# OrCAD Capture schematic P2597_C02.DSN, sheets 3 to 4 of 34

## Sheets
3 31_Power Monitor I: size Custom
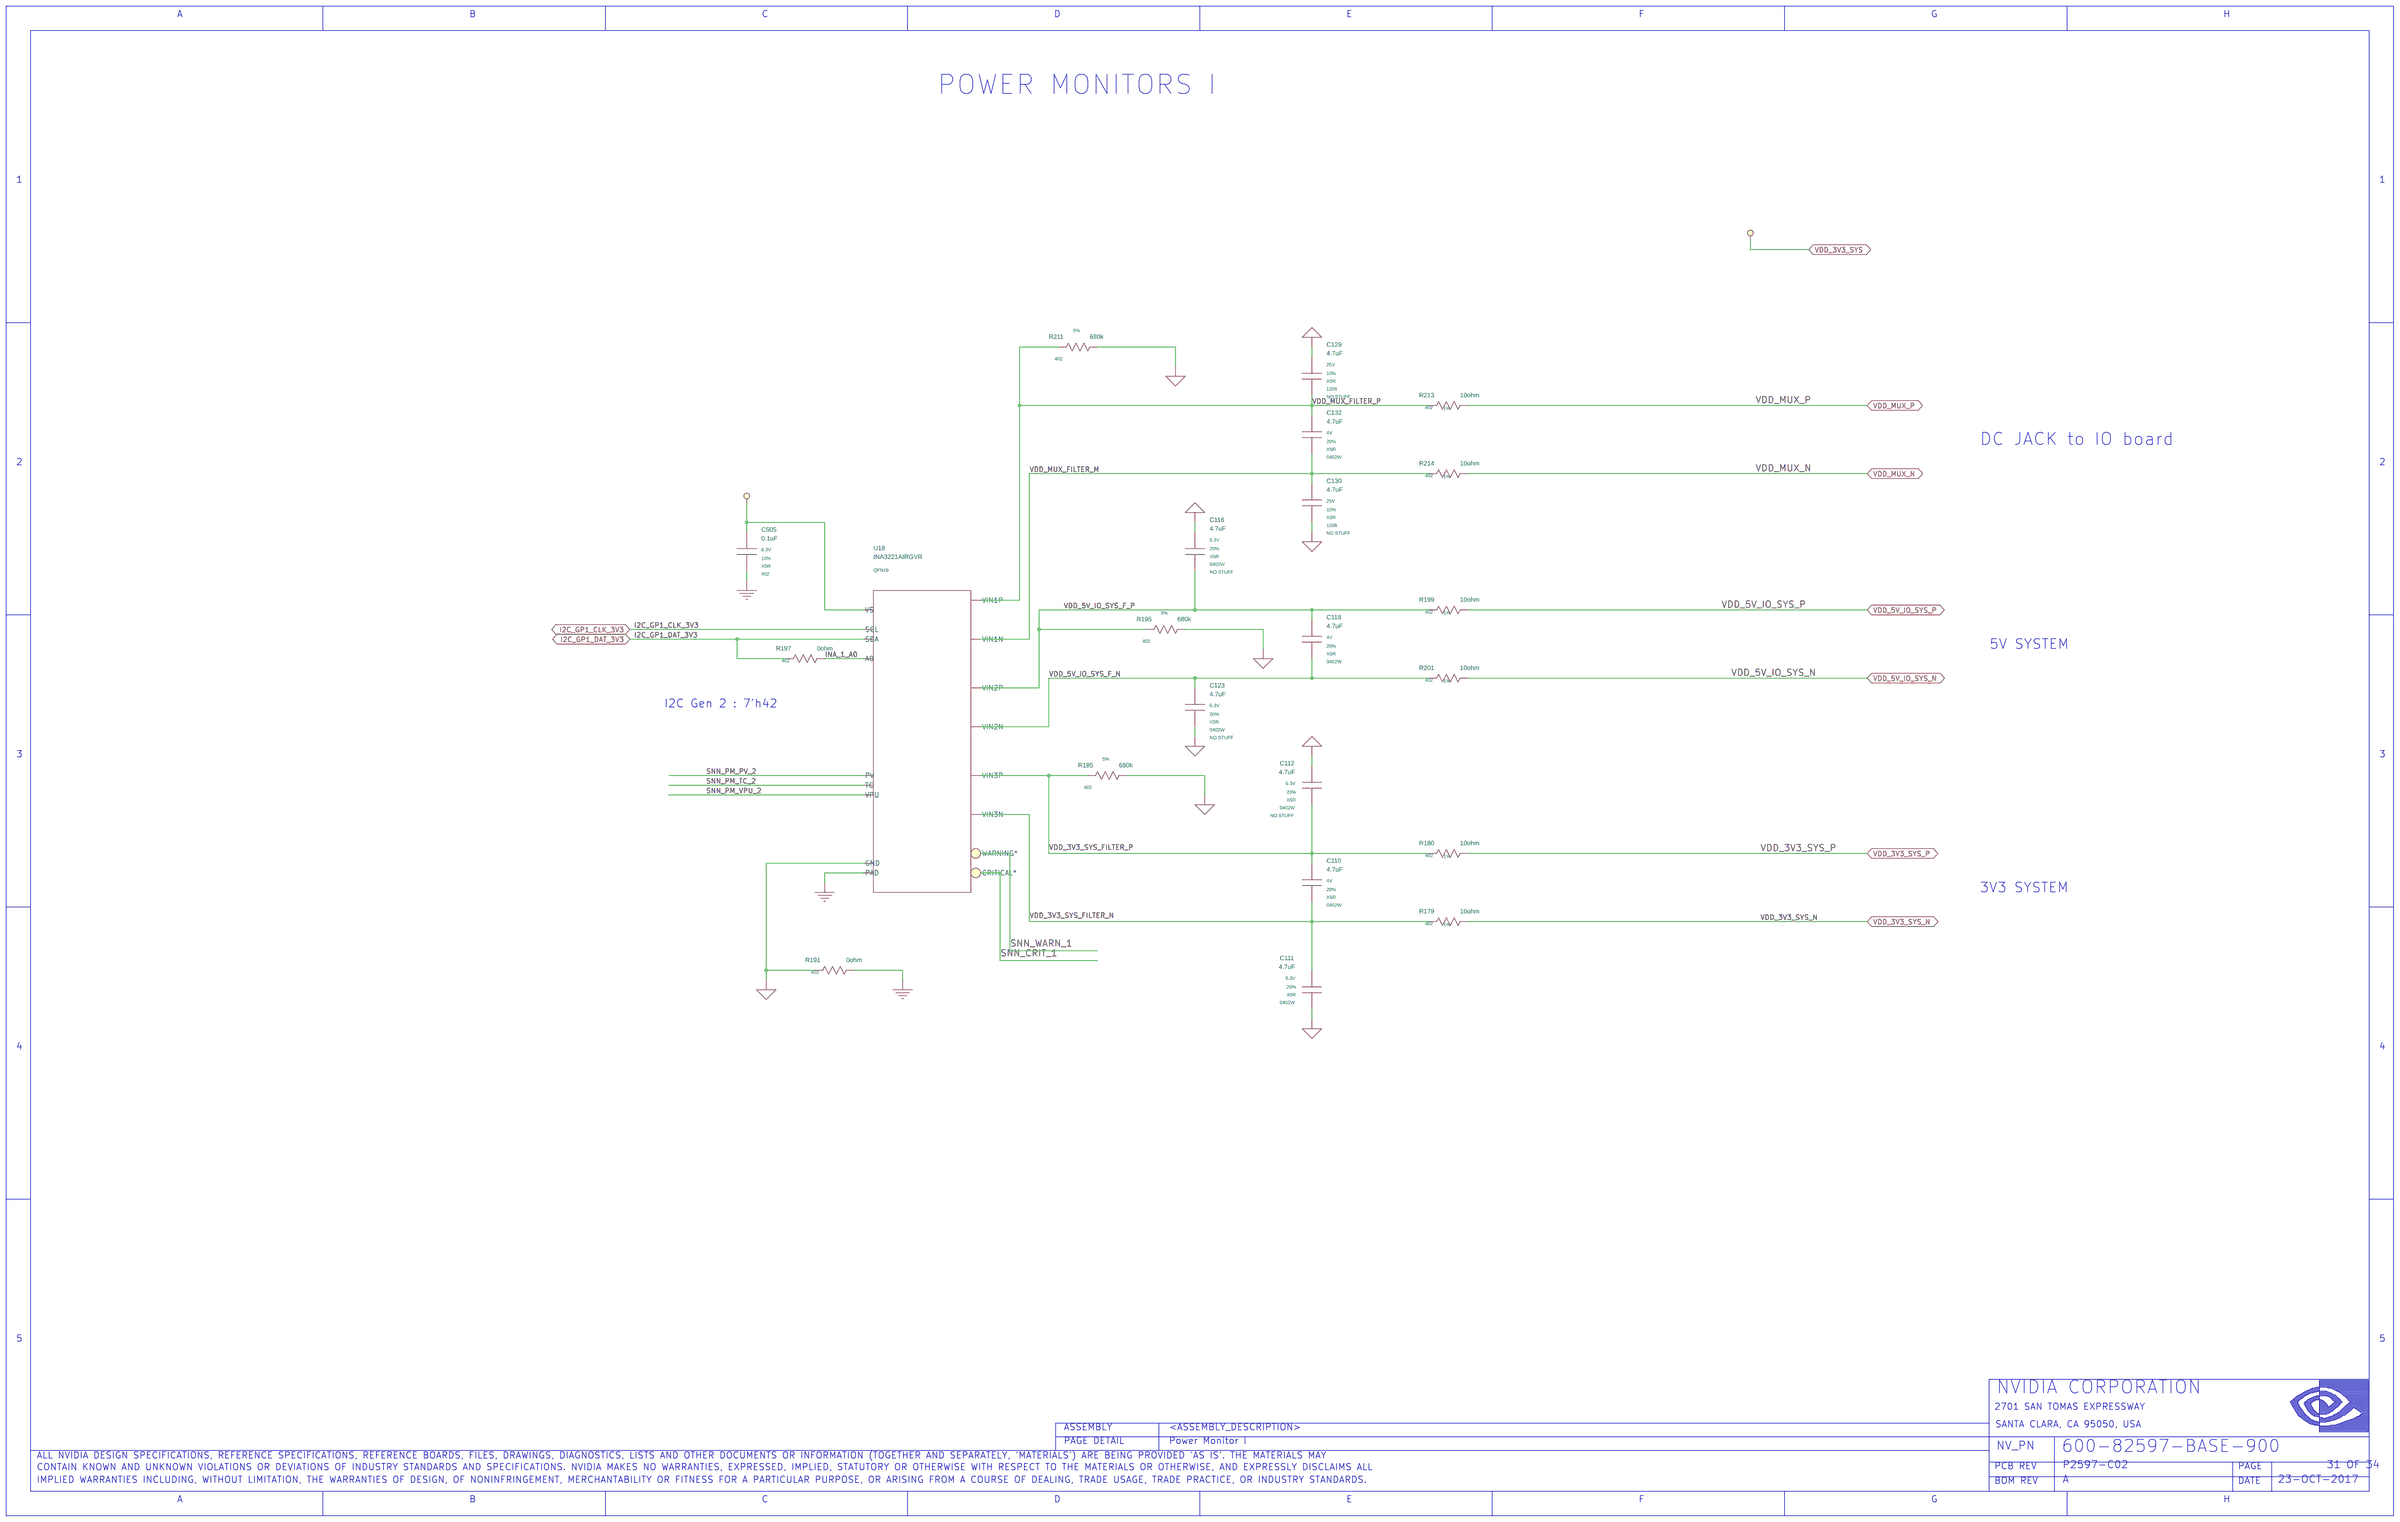
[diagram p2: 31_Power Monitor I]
4 30_Rail Discharge: size Custom
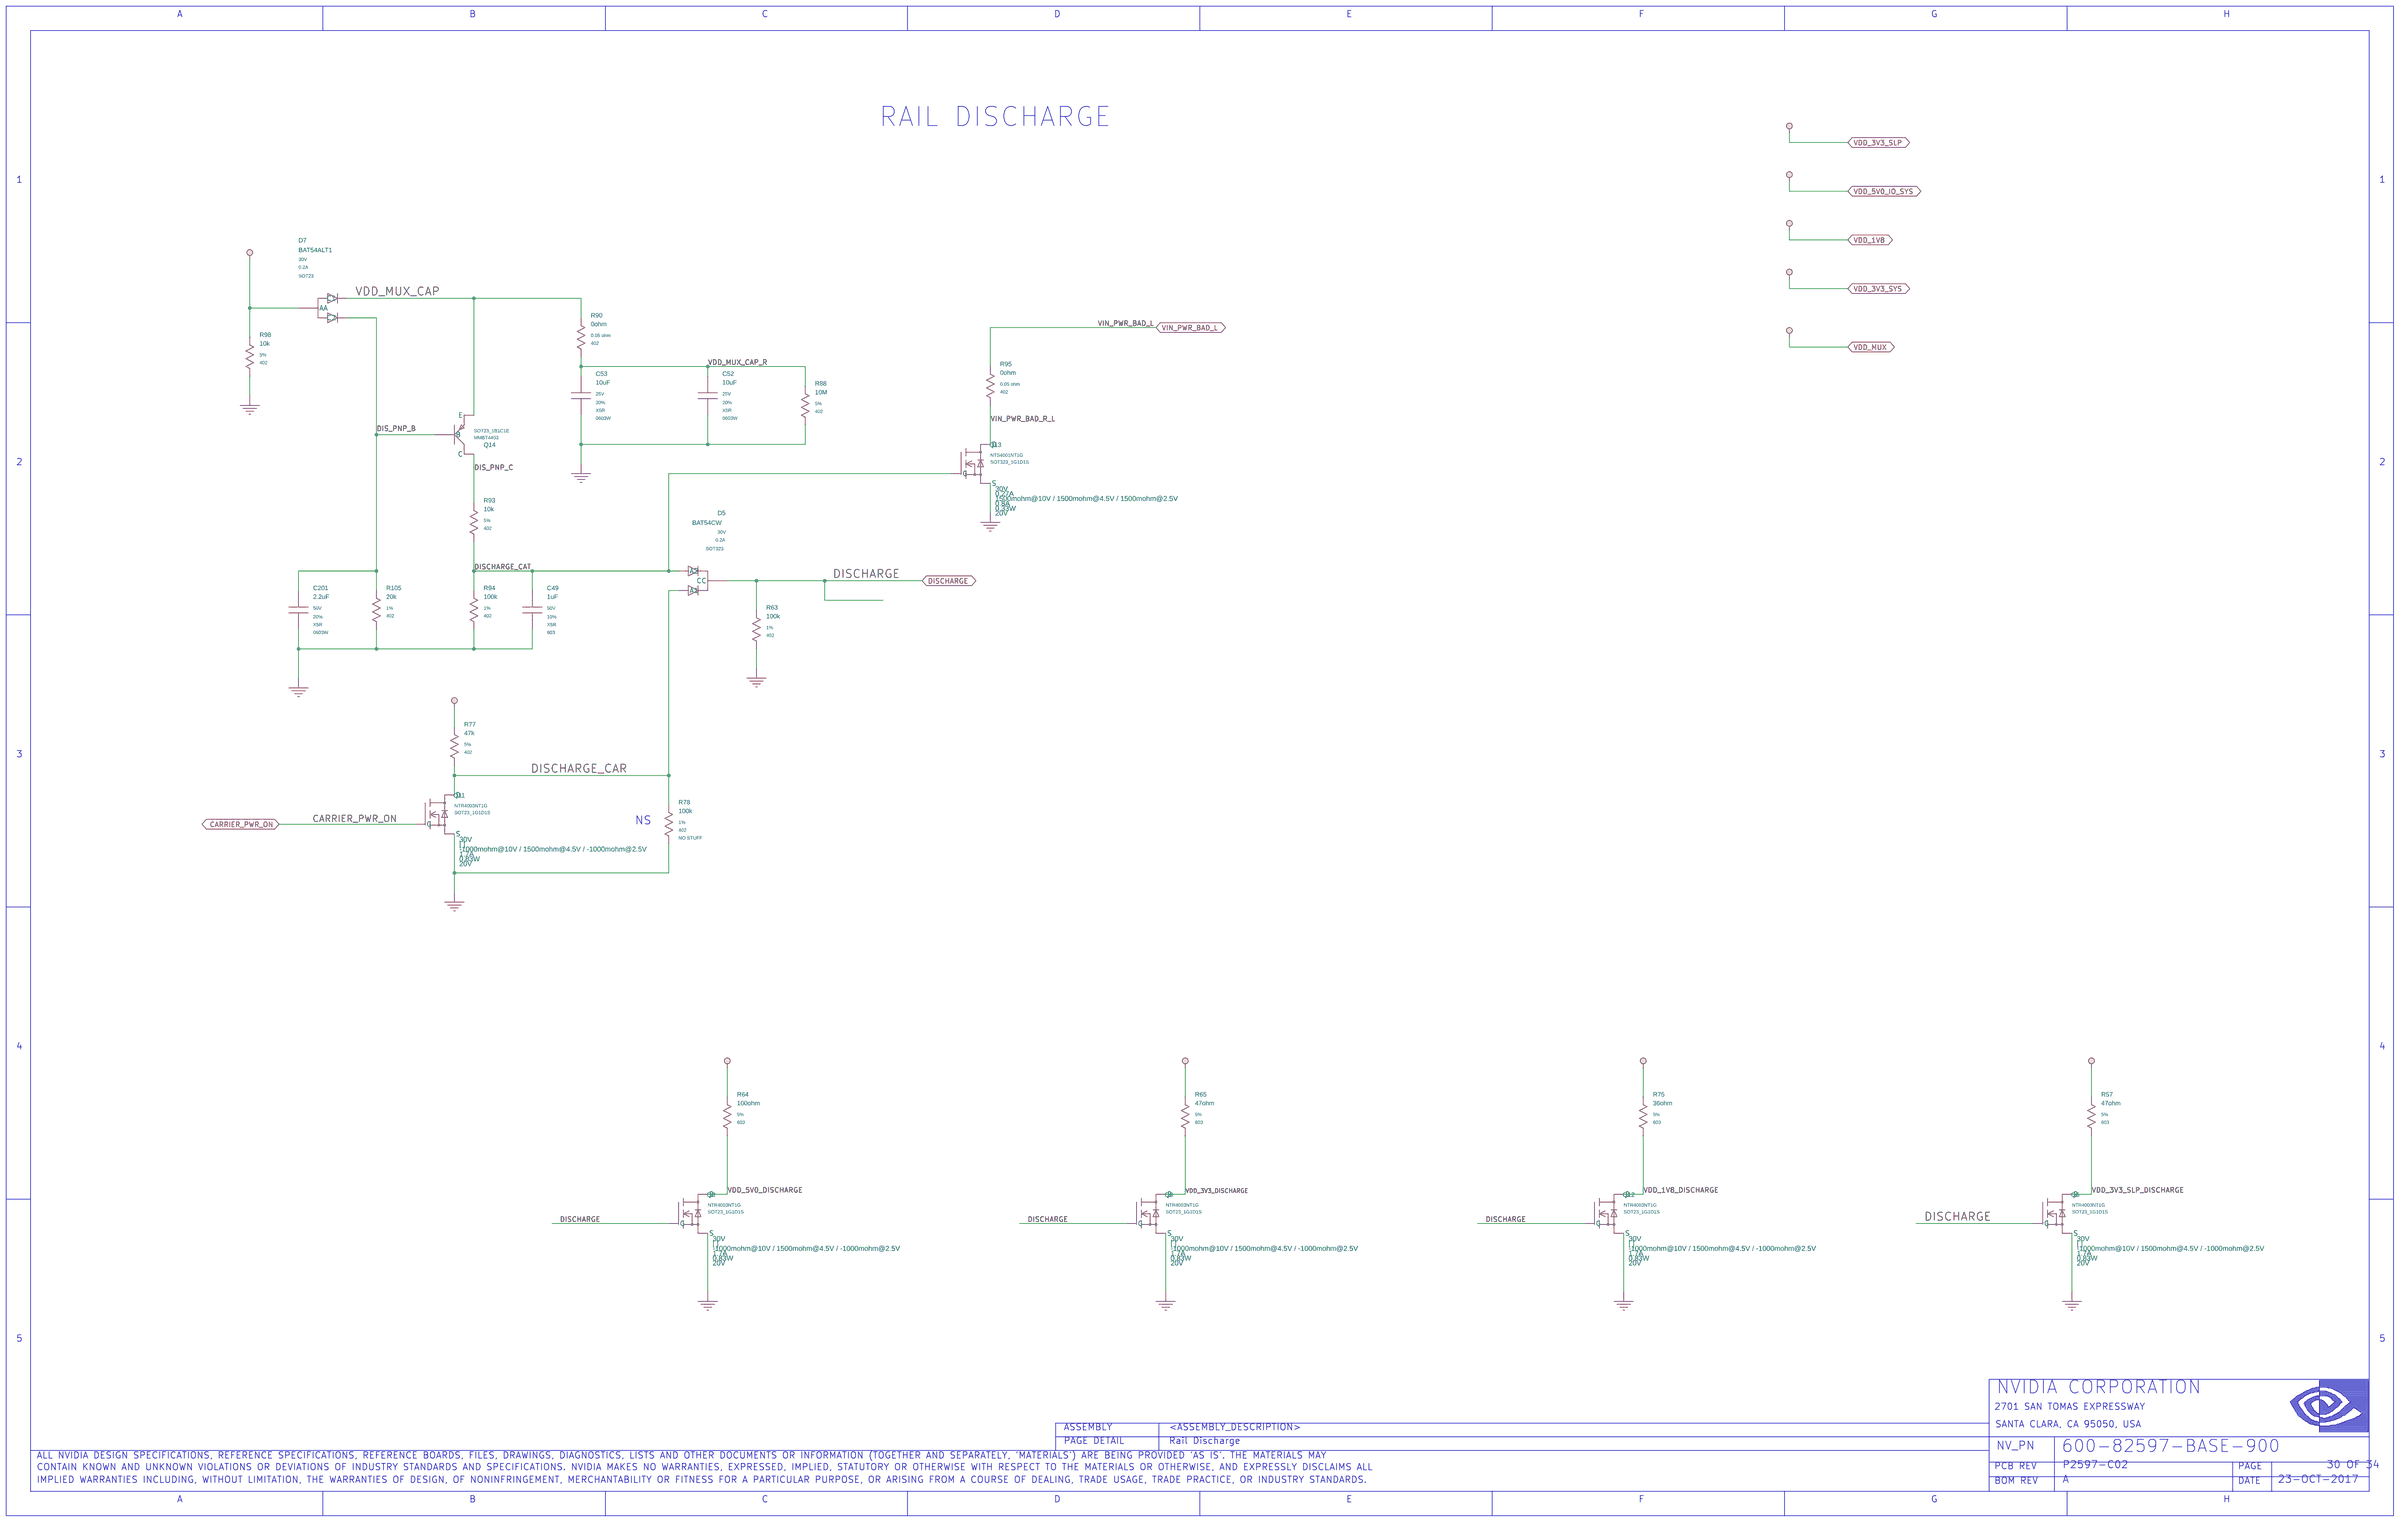
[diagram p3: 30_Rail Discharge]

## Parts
sheet 30_Rail Discharge
C49  1uF  [603]
C52  10uF  [0603_LARGE]
C53  10uF  [0603_LARGE]
C201  2.2uF  [0603_LARGE]
D5  D_3PIN_CC  [SOT323]
D7  D_3PIN_AA  [SOT23]
Q6  Q_FET_N_ENH  [SOT23]
Q8  Q_FET_N_ENH  [SOT23]
Q9  Q_FET_N_ENH  [SOT23]
Q11  Q_FET_N_ENH  [SOT23]
Q12  Q_FET_N_ENH  [SOT23]
Q13  Q_FET_N_ENH  [SOT323]
Q14  Q_PNP  [SOT23]
R57  47ohm  [603]
R63  100k  [402]
R64  100ohm  [603]
R65  47ohm  [603]
R75  36ohm  [603]
R77  47k  [402]
R78  100k  [402]
R88  10M  [402]
R90  0ohm  [402]
R93  10k  [402]
R94  100k  [402]
R95  0ohm  [402]
R98  10k  [402]
R105  20k  [402]
sheet 31_Power Monitor I
C110  4.7uF  [0402_LARGE]
C111  4.7uF  [0402_LARGE]
C112  4.7uF  [0402_LARGE]
C116  4.7uF  [0402_LARGE]
C118  4.7uF  [0402_LARGE]
C123  4.7uF  [0402_LARGE]
C129  4.7uF  [1206]
C130  4.7uF  [1206]
C132  4.7uF  [0402_LARGE]
C505  0.1uF  [402]
R179  10ohm  [402]
R180  10ohm  [402]
R185  680k  [402]
R191  0ohm  [402]
R195  680k  [402]
R197  0ohm  [402]
R199  10ohm  [402]
R201  10ohm  [402]
R211  680k  [402]
R213  10ohm  [402]
R214  10ohm  [402]
U18  U_PWRMTR_INA3221  [QFN016Q_P065_0047_T022X022]

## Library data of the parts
C49 = C: ASSEMBLY: PWR_DIS; CDS_LIB: discrete; CDS_PART_NAME: C_0603-1UF,X5R,10%,50V,039-0222-000; CDS_PHYS_PART_NAME: C_0603-1UF,X5R,10%,50V,039-0222-000-039-0222-000,1UF; CDS_SEC: 1; DEVICE_TYPENAME: C_0603-1UFX5R1050V039-0222-000-039-0222-0001UF; DRAWING: @P2597_C02_LIB.P2597_C02(SCH_1):PAGE30; MAT: X5R; MAX_VOLTAGE: 50V; NV_PN: 039-0222-000; PATH: I14; PHYS_PAGE: 30; ROT: 0; SEC: 1; SIGNAL_MODEL: nv_cap; TOL: 10%; VER: 1; XY: (-9450,4500)
C52 = C: ASSEMBLY: PWR_DIS; CDS_LIB: discrete; CDS_PART_NAME: C_0603W-10UF,X5R,20%,25V,032-0186-000; CDS_PHYS_PART_NAME: C_0603W-10UF,X5R,20%,25V,032-0186-000-032-0186-000,10UF; CDS_SEC: 1; DEVICE_TYPENAME: C_0603W-10UFX5R2025V032-0186-000-032-0186-00010UF; DRAWING: @P2597_C02_LIB.P2597_C02(SCH_1):PAGE30; MAT: X5R; MAX_VOLTAGE: 25V; NV_PN: 032-0186-000; PACK_TYPE: 0603W; PATH: I35; PHYS_PAGE: 30; ROT: 0; SEC: 1; SIGNAL_MODEL: nv_cap; TOL: 20%; VER: 1; XY: (-8550,5600)
C53 = C: ASSEMBLY: PWR_DIS; CDS_LIB: discrete; CDS_PART_NAME: C_0603W-10UF,X5R,20%,25V,032-0186-000; CDS_PHYS_PART_NAME: C_0603W-10UF,X5R,20%,25V,032-0186-000-032-0186-000,10UF; CDS_SEC: 1; DEVICE_TYPENAME: C_0603W-10UFX5R2025V032-0186-000-032-0186-00010UF; DRAWING: @P2597_C02_LIB.P2597_C02(SCH_1):PAGE30; MAT: X5R; MAX_VOLTAGE: 25V; NV_PN: 032-0186-000; PACK_TYPE: 0603W; PATH: I36; PHYS_PAGE: 30; ROT: 0; SEC: 1; SIGNAL_MODEL: nv_cap; TOL: 20%; VER: 1; XY: (-9200,5600)
C201 = C: ASSEMBLY: PWR_DIS; CDS_LIB: discrete; CDS_PART_NAME: C_0603W-2.2UF,X5R,20%,50V,032-0201-000; CDS_PHYS_PART_NAME: C_0603W-2.2UF,X5R,20%,50V,032-0201-000-032-0201-000,2.2UF; CDS_SEC: 1; DEVICE_TYPENAME: C_0603W-22UFX5R2050V032-0201-000-032-0201-00022UF; DRAWING: @P2597_C02_LIB.P2597_C02(SCH_1):PAGE30; MAT: X5R; MAX_VOLTAGE: 50V; NV_PN: 032-0201-000; PACK_TYPE: 0603W; PATH: I68; PHYS_PAGE: 30; ROT: 0; SEC: 1; SEC_TYPE: 0603W; SIGNAL_MODEL: nv_cap; TOL: 20%; VER: 1; XY: (-10650,4500)
D5 = D_3PIN_CC: ASSEMBLY: PWR_DIS; CDS_LIB: discrete; CDS_PART_NAME: D_3PIN_CC_SOT323-BAT54CW,1 PAIR - COMMON CATHODE,30V,0.6A,1V@0.1A,0.2A,091-0022-000; CDS_PHYS_PART_NAME: D_3PIN_CC_SOT323-BAT54CW,1 PAIR - COMMON CATHODE,30V,0.6A,1V@0.1A,0.2A,091-0022-000-091-0022-000; CDS_SEC: 1; CONFIGURATION: 1 Pair - Common Cathode; CONTINUOUS_CURRENT: 0.2A; DEVICE_TYPENAME: D_3PIN_CC_SOT323-BAT54CW1PAIR-COMMONCATHODE30V06A1V01A02A091-0022-000-091-0022-000; DRAWING: @P2597_C02_LIB.P2597_C02(SCH_1):PAGE30; FORWARD_VOLTAGE: 1V@0.1A; MAX_CURRENT: 0.6A; MAX_VOLTAGE: 30V; NV_NAME: BAT54CW; NV_PN: 091-0022-000; PATH: I46; PHYS_PAGE: 30; ROT: 2; SEC: 1; VER: 1; XY: (-8550,4650)
D7 = D_3PIN_AA: ASSEMBLY: PWR_DIS; CDS_LIB: discrete; CDS_PART_NAME: D_3PIN_AA_SOT23-BAT54ALT1,1 PAIR - COMMON ANODE,30V,0.6A,0.8V@0.1A,0.2A,091-0004-000; CDS_PHYS_PART_NAME: D_3PIN_AA_SOT23-BAT54ALT1,1 PAIR - COMMON ANODE,30V,0.6A,0.8V@0.1A,0.2A,091-0004-000-091-0004-000; CDS_SEC: 1; CONFIGURATION: 1 Pair - Common Anode; CONTINUOUS_CURRENT: 0.2A; DEVICE_TYPENAME: D_3PIN_AA_SOT23-BAT54ALT11PAIR-COMMONANODE30V06A08V01A02A091-0004-000-091-0004-000; DRAWING: @P2597_C02_LIB.P2597_C02(SCH_1):PAGE30; FORWARD_VOLTAGE: 0.8V@0.1A; MAX_CURRENT: 0.6A; MAX_VOLTAGE: 30V; NV_NAME: BAT54ALT1; NV_PN: 091-0004-000; PATH: I2; PHYS_PAGE: 30; ROT: 0; SEC: 1; VER: 1; XY: (-10550,6050)
Q6 = Q_FET_N_ENH#2: ASSEMBLY: PWR_DIS; CDS_LIB: discrete; CDS_PART_NAME: Q_FET_N_ENH_SOT23_1G1D1S-NTR4003NT1G,30V,-1000MOHM@10V / 1500MOHM@4.5V / -1000MOHM@2.5V,[ ],1.7A,20V,0.83W,[ ]@10V / [ ]@4.5V A; CDS_PHYS_PART_NAME: Q_FET_N_ENH_SOT23_1G1D1S-NTR4003NT1G,30V,-1000MOHM@10V / 1500MOHM@4.5V / -1000MOHM@2.5V,[ ],1.7A,20V,0.83W,[ ]@10V / [ ]@4.5V B; CDS_SEC: 1; CONTINUOUS_CURRENT: [ ]; CaptureCellPackProp: Q_FET_N_ENH__sym_2##2; DEVICE_TYPENAME: Q_FET_N_ENH_SOT23_1G1D1S-NTR4003NT1G30V-1000MOHM10V1500MOHM45V-1000MOHM25V17A20V083W10V45VB; DRAWING: @P2597_C02_LIB.P2597_C02(SCH_1):PAGE30; MAX_CURRENT: 1.7A; MAX_VOLTAGE: 30V; MAX_WATTAGE: 0.83W; NV_NAME: NTR4003NT1G; NV_PN: 300-0381-000; PACK_TYPE: SOT23_1G1D1S; PATH: I43; PHYS_PAGE: 30; Q_G: [ ]@10V / [ ]@4.5V / [ ]@2.5V; ROT: 0; R_DS_ON: -1000mohm@10V / 1500mohm@4.5V / -1000mohm@2.5V; SEC: 1; VER: 2; V_BE_GS: 20V; XY: (-1650,1400)
Q8 = Q_FET_N_ENH#2: ASSEMBLY: PWR_DIS; CDS_LIB: discrete; CDS_PART_NAME: Q_FET_N_ENH_SOT23_1G1D1S-NTR4003NT1G,30V,-1000MOHM@10V / 1500MOHM@4.5V / -1000MOHM@2.5V,[ ],1.7A,20V,0.83W,[ ]@10V / [ ]@4.5V A; CDS_PHYS_PART_NAME: Q_FET_N_ENH_SOT23_1G1D1S-NTR4003NT1G,30V,-1000MOHM@10V / 1500MOHM@4.5V / -1000MOHM@2.5V,[ ],1.7A,20V,0.83W,[ ]@10V / [ ]@4.5V B; CDS_SEC: 1; CONTINUOUS_CURRENT: [ ]; CaptureCellPackProp: Q_FET_N_ENH__sym_2##2; DEVICE_TYPENAME: Q_FET_N_ENH_SOT23_1G1D1S-NTR4003NT1G30V-1000MOHM10V1500MOHM45V-1000MOHM25V17A20V083W10V45VB; DRAWING: @P2597_C02_LIB.P2597_C02(SCH_1):PAGE30; MAX_CURRENT: 1.7A; MAX_VOLTAGE: 30V; MAX_WATTAGE: 0.83W; NV_NAME: NTR4003NT1G; NV_PN: 300-0381-000; PACK_TYPE: SOT23_1G1D1S; PATH: I17; PHYS_PAGE: 30; Q_G: [ ]@10V / [ ]@4.5V / [ ]@2.5V; ROT: 0; R_DS_ON: -1000mohm@10V / 1500mohm@4.5V / -1000mohm@2.5V; SEC: 1; VER: 2; V_BE_GS: 20V; XY: (-8650,1400)
Q9 = Q_FET_N_ENH#2: ASSEMBLY: PWR_DIS; CDS_LIB: discrete; CDS_PART_NAME: Q_FET_N_ENH_SOT23_1G1D1S-NTR4003NT1G,30V,-1000MOHM@10V / 1500MOHM@4.5V / -1000MOHM@2.5V,[ ],1.7A,20V,0.83W,[ ]@10V / [ ]@4.5V A; CDS_PHYS_PART_NAME: Q_FET_N_ENH_SOT23_1G1D1S-NTR4003NT1G,30V,-1000MOHM@10V / 1500MOHM@4.5V / -1000MOHM@2.5V,[ ],1.7A,20V,0.83W,[ ]@10V / [ ]@4.5V B; CDS_SEC: 1; CONTINUOUS_CURRENT: [ ]; CaptureCellPackProp: Q_FET_N_ENH__sym_2##2; DEVICE_TYPENAME: Q_FET_N_ENH_SOT23_1G1D1S-NTR4003NT1G30V-1000MOHM10V1500MOHM45V-1000MOHM25V17A20V083W10V45VB; DRAWING: @P2597_C02_LIB.P2597_C02(SCH_1):PAGE30; MAX_CURRENT: 1.7A; MAX_VOLTAGE: 30V; MAX_WATTAGE: 0.83W; NV_NAME: NTR4003NT1G; NV_PN: 300-0381-000; PACK_TYPE: SOT23_1G1D1S; PATH: I24; PHYS_PAGE: 30; Q_G: [ ]@10V / [ ]@4.5V / [ ]@2.5V; ROT: 0; R_DS_ON: -1000mohm@10V / 1500mohm@4.5V / -1000mohm@2.5V; SEC: 1; VER: 2; V_BE_GS: 20V; XY: (-6300,1400)
Q11 = Q_FET_N_ENH#2: ASSEMBLY: PWR_DIS; CDS_LIB: discrete; CDS_PART_NAME: Q_FET_N_ENH_SOT23_1G1D1S-NTR4003NT1G,30V,-1000MOHM@10V / 1500MOHM@4.5V / -1000MOHM@2.5V,[ ],1.7A,20V,0.83W,[ ]@10V / [ ]@4.5V A; CDS_PHYS_PART_NAME: Q_FET_N_ENH_SOT23_1G1D1S-NTR4003NT1G,30V,-1000MOHM@10V / 1500MOHM@4.5V / -1000MOHM@2.5V,[ ],1.7A,20V,0.83W,[ ]@10V / [ ]@4.5V B; CDS_SEC: 1; CONTINUOUS_CURRENT: [ ]; CaptureCellPackProp: Q_FET_N_ENH__sym_2##2; DEVICE_TYPENAME: Q_FET_N_ENH_SOT23_1G1D1S-NTR4003NT1G30V-1000MOHM10V1500MOHM45V-1000MOHM25V17A20V083W10V45VB; DRAWING: @P2597_C02_LIB.P2597_C02(SCH_1):PAGE30; MAX_CURRENT: 1.7A; MAX_VOLTAGE: 30V; MAX_WATTAGE: 0.83W; NV_NAME: NTR4003NT1G; NV_PN: 300-0381-000; PACK_TYPE: SOT23_1G1D1S; PATH: I47; PHYS_PAGE: 30; Q_G: [ ]@10V / [ ]@4.5V / [ ]@2.5V; ROT: 0; R_DS_ON: -1000mohm@10V / 1500mohm@4.5V / -1000mohm@2.5V; SEC: 1; VER: 2; V_BE_GS: 20V; XY: (-9950,3450)
Q12 = Q_FET_N_ENH#2: ASSEMBLY: PWR_DIS; CDS_LIB: discrete; CDS_PART_NAME: Q_FET_N_ENH_SOT23_1G1D1S-NTR4003NT1G,30V,-1000MOHM@10V / 1500MOHM@4.5V / -1000MOHM@2.5V,[ ],1.7A,20V,0.83W,[ ]@10V / [ ]@4.5V A; CDS_PHYS_PART_NAME: Q_FET_N_ENH_SOT23_1G1D1S-NTR4003NT1G,30V,-1000MOHM@10V / 1500MOHM@4.5V / -1000MOHM@2.5V,[ ],1.7A,20V,0.83W,[ ]@10V / [ ]@4.5V B; CDS_SEC: 1; CONTINUOUS_CURRENT: [ ]; CaptureCellPackProp: Q_FET_N_ENH__sym_2##2; DEVICE_TYPENAME: Q_FET_N_ENH_SOT23_1G1D1S-NTR4003NT1G30V-1000MOHM10V1500MOHM45V-1000MOHM25V17A20V083W10V45VB; DRAWING: @P2597_C02_LIB.P2597_C02(SCH_1):PAGE30; MAX_CURRENT: 1.7A; MAX_VOLTAGE: 30V; MAX_WATTAGE: 0.83W; NV_NAME: NTR4003NT1G; NV_PN: 300-0381-000; PACK_TYPE: SOT23_1G1D1S; PATH: I29; PHYS_PAGE: 30; Q_G: [ ]@10V / [ ]@4.5V / [ ]@2.5V; ROT: 0; R_DS_ON: -1000mohm@10V / 1500mohm@4.5V / -1000mohm@2.5V; SEC: 1; VER: 2; V_BE_GS: 20V; XY: (-3950,1400)
Q13 = Q_FET_N_ENH#2: ASSEMBLY: CONN_POWER; CDS_LIB: discrete; CDS_PART_NAME: Q_FET_N_ENH_SOT323_1G1D1S-NTS4001NT1G,30V,1500MOHM@10V / 1500MOHM@4.5V / 1500MOHM@2.5V,0.27A,0.8A,20V,0.33W,[ ]@10V / [ ]@4.5VA; CDS_PHYS_PART_NAME: Q_FET_N_ENH_SOT323_1G1D1S-NTS4001NT1G,30V,1500MOHM@10V / 1500MOHM@4.5V / 1500MOHM@2.5V,0.27A,0.8A,20V,0.33W,[ ]@10V / [ ]@4.5VB; CDS_SEC: 1; CONTINUOUS_CURRENT: 0.27A; CaptureCellPackProp: Q_FET_N_ENH__sym_2##2; DEVICE_TYPENAME: Q_FET_N_ENH_SOT323_1G1D1S-NTS4001NT1G30V1500MOHM10V1500MOHM45V1500MOHM25V027A08A20V033W10V45VB; DRAWING: @P2597_C02_LIB.P2597_C02(SCH_1):PAGE30; MAX_CURRENT: 0.8A; MAX_VOLTAGE: 30V; MAX_WATTAGE: 0.33W; NV_NAME: NTS4001NT1G; NV_PN: 300-0485-000; PACK_TYPE: SOT323_1G1D1S; PATH: I38; PHYS_PAGE: 30; Q_G: [ ]@10V / [ ]@4.5V / [ ]@2.5V; ROT: 0; R_DS_ON: 1500mohm@10V / 1500mohm@4.5V / 1500mohm@2.5V; SEC: 1; SEC_TYPE: SOT323_1G1D1S; VER: 2; V_BE_GS: 20V; XY: (-7200,5250)
Q14 = Q_PNP: ASSEMBLY: PWR_DIS; CDS_LIB: discrete; CDS_PART_NAME: Q_PNP_SOT23_1B1C1E-MMBT4403,40V,[ ],0.6A,0.6A,5V,0.225W,305-0002-000; CDS_PHYS_PART_NAME: Q_PNP_SOT23_1B1C1E-MMBT4403,40V,[ ],0.6A,0.6A,5V,0.225W,305-0002-000-305-0002-000; CDS_SEC: 1; CONTINUOUS_CURRENT: 0.6A; DEVICE_TYPENAME: Q_PNP_SOT23_1B1C1E-MMBT440340V06A06A5V0225W305-0002-000-305-0002-000; DRAWING: @P2597_C02_LIB.P2597_C02(SCH_1):PAGE30; MAX_CURRENT: 0.6A; MAX_VOLTAGE: 40V; MAX_WATTAGE: 0.225W; NV_NAME: MMBT4403; NV_PN: 305-0002-000; PACK_TYPE: SOT23_1B1C1E; PATH: I5; PHYS_PAGE: 30; ROT: 6; SEC: 1; VER: 1; V_BE_GS: 5V; V_CE_SAT: [ ]; XY: (-9850,5400)
R57 = R#1: ASSEMBLY: PWR_DIS; CDS_LIB: discrete; CDS_PART_NAME: R_0603-47OHM,5 %,0.1W,195-1246-000; CDS_PHYS_PART_NAME: R_0603-47OHM,5 %,0.1W,195-1246-000-195-1246-000,47OHM; CDS_SEC: 1; CHIPS_PART_NAME: R; DEVICE_TYPENAME: R_0603-47OHM501W195-1246-000-195-1246-00047OHM; DRAWING: @P2597_C02_LIB.P2597_C02(SCH_1):PAGE30; MAX_WATTAGE: 0.1W; NV_PN: 195-1246-000; PATH: I42; PHYS_PAGE: 30; ROT: 0; SEC: 1; SIGNAL_MODEL: nv_res; TOL: 5%; VER: 2; XY: (-1450,1900)
R63 = R#1: ASSEMBLY: PWR_DIS; CDS_LIB: discrete; CDS_PART_NAME: R_0402-100K,1 %,62.5MW,195-0005-000; CDS_PHYS_PART_NAME: R_0402-100K,1 %,62.5MW,195-0005-000-100K,195-0005-000; CDS_SEC: 1; CHIPS_PART_NAME: R; DEVICE_TYPENAME: R_0402-100K1625MW195-0005-000-100K195-0005-000; DRAWING: @P2597_C02_LIB.P2597_C02(SCH_1):PAGE30; MAX_WATTAGE: 62.5mW; NV_PN: 195-0005-000; PATH: I53; PHYS_PAGE: 30; ROT: 0; SEC: 1; SIGNAL_MODEL: nv_res; TOL: 1%; VER: 2; XY: (-8300,4400)
R64 = R#1: ASSEMBLY: PWR_DIS; CDS_LIB: discrete; CDS_PART_NAME: R_0603-100OHM,5 %,0.1W,195-1134-000; CDS_PHYS_PART_NAME: R_0603-100OHM,5 %,0.1W,195-1134-000-100OHM,195-1134-000; CDS_SEC: 1; CHIPS_PART_NAME: R; DEVICE_TYPENAME: R_0603-100OHM501W195-1134-000-100OHM195-1134-000; DRAWING: @P2597_C02_LIB.P2597_C02(SCH_1):PAGE30; MAX_WATTAGE: 0.1W; NV_PN: 195-1134-000; PATH: I19; PHYS_PAGE: 30; ROT: 0; SEC: 1; SIGNAL_MODEL: nv_res; TOL: 5%; VER: 2; XY: (-8450,1900)
R65 = R#1: ASSEMBLY: PWR_DIS; CDS_LIB: discrete; CDS_PART_NAME: R_0603-47OHM,5 %,0.1W,195-1246-000; CDS_PHYS_PART_NAME: R_0603-47OHM,5 %,0.1W,195-1246-000-195-1246-000,47OHM; CDS_SEC: 1; CHIPS_PART_NAME: R; DEVICE_TYPENAME: R_0603-47OHM501W195-1246-000-195-1246-00047OHM; DRAWING: @P2597_C02_LIB.P2597_C02(SCH_1):PAGE30; MAX_WATTAGE: 0.1W; NV_PN: 195-1246-000; PATH: I23; PHYS_PAGE: 30; ROT: 0; SEC: 1; SIGNAL_MODEL: nv_res; TOL: 5%; VER: 2; XY: (-6100,1900)
R75 = R#1: ASSEMBLY: PWR_DIS; CDS_LIB: discrete; CDS_PART_NAME: R_0603-36OHM,5 %,0.1W,195-1225-000; CDS_PHYS_PART_NAME: R_0603-36OHM,5 %,0.1W,195-1225-000-195-1225-000,36OHM; CDS_SEC: 1; CHIPS_PART_NAME: R; DEVICE_TYPENAME: R_0603-36OHM501W195-1225-000-195-1225-00036OHM; DRAWING: @P2597_C02_LIB.P2597_C02(SCH_1):PAGE30; MAX_WATTAGE: 0.1W; NV_PN: 195-1225-000; PATH: I28; PHYS_PAGE: 30; ROT: 0; SEC: 1; SIGNAL_MODEL: nv_res; TOL: 5%; VER: 2; XY: (-3750,1900)
R77 = R#1: ASSEMBLY: PWR_DIS; CDS_LIB: discrete; CDS_PART_NAME: R_0402-47K,5 %,62.5MW,195-0599-000; CDS_PHYS_PART_NAME: R_0402-47K,5 %,62.5MW,195-0599-000-195-0599-000,47K; CDS_SEC: 1; CHIPS_PART_NAME: R; DEVICE_TYPENAME: R_0402-47K5625MW195-0599-000-195-0599-00047K; DRAWING: @P2597_C02_LIB.P2597_C02(SCH_1):PAGE30; MAX_WATTAGE: 62.5mW; NV_PN: 195-0599-000; PATH: I49; PHYS_PAGE: 30; ROT: 0; SEC: 1; SIGNAL_MODEL: nv_res; TOL: 5%; VER: 2; XY: (-9850,3800)
R78 = R#1: ASSEMBLY: PWR_DIS; CDS_LIB: discrete; CDS_PART_NAME: R_0402-100K,1 %,62.5MW,195-0005-000; CDS_PHYS_PART_NAME: R_0402-100K,1 %,62.5MW,195-0005-000-100K,195-0005-000; CDS_SEC: 1; CHIPS_PART_NAME: R; DEVICE_TYPENAME: R_0402-100K1625MW195-0005-000-100K195-0005-000; DRAWING: @P2597_C02_LIB.P2597_C02(SCH_1):PAGE30; MAX_WATTAGE: 62.5mW; NV_PN: 195-0005-000; PATH: I50; PHYS_PAGE: 30; ROT: 0; SEC: 1; SIGNAL_MODEL: nv_res; SKU: NO STUFF; TOL: 1%; VER: 2; XY: (-8750,3400)
R88 = R#1: ASSEMBLY: PWR_DIS; CDS_LIB: discrete; CDS_PART_NAME: R_0402-10M,5 %,62.5MW,195-0489-000; CDS_PHYS_PART_NAME: R_0402-10M,5 %,62.5MW,195-0489-000-10M,195-0489-000; CDS_SEC: 1; CHIPS_PART_NAME: R; DEVICE_TYPENAME: R_0402-10M5625MW195-0489-000-10M195-0489-000; DRAWING: @P2597_C02_LIB.P2597_C02(SCH_1):PAGE30; MAX_WATTAGE: 62.5mW; NV_PN: 195-0489-000; PATH: I8; PHYS_PAGE: 30; ROT: 0; SEC: 1; SIGNAL_MODEL: nv_res; TOL: 5%; VER: 2; XY: (-8050,5550)
R90 = R#1: ASSEMBLY: PWR_DIS; CDS_LIB: discrete; CDS_PART_NAME: R_0402-0OHM,0.05 OHM,62.5MW,195-2655-000; CDS_PHYS_PART_NAME: R_0402-0OHM,0.05 OHM,62.5MW,195-2655-000-0OHM,195-2655-000; CDS_SEC: 1; CHIPS_PART_NAME: R; DEVICE_TYPENAME: R_0402-0OHM005OHM625MW195-2655-000-0OHM195-2655-000; DRAWING: @P2597_C02_LIB.P2597_C02(SCH_1):PAGE30; MAX_WATTAGE: 62.5mW; NV_PN: 195-2655-000; PATH: I9; PHYS_PAGE: 30; ROT: 0; SEC: 1; SIGNAL_MODEL: nv_res; TOL: 0.05 ohm; VER: 2; XY: (-9200,5900)
R93 = R#1: ASSEMBLY: PWR_DIS; CDS_LIB: discrete; CDS_PART_NAME: R_0402-10K,5 %,62.5MW,195-0486-000; CDS_PHYS_PART_NAME: R_0402-10K,5 %,62.5MW,195-0486-000-10K,195-0486-000; CDS_SEC: 1; CHIPS_PART_NAME: R; DEVICE_TYPENAME: R_0402-10K5625MW195-0486-000-10K195-0486-000; DRAWING: @P2597_C02_LIB.P2597_C02(SCH_1):PAGE30; MAX_WATTAGE: 62.5mW; NV_PN: 195-0486-000; PATH: I12; PHYS_PAGE: 30; ROT: 0; SEC: 1; SIGNAL_MODEL: nv_res; TOL: 5%; VER: 2; XY: (-9750,4950)
R94 = R#1: ASSEMBLY: PWR_DIS; CDS_LIB: discrete; CDS_PART_NAME: R_0402-100K,1 %,62.5MW,195-0005-000; CDS_PHYS_PART_NAME: R_0402-100K,1 %,62.5MW,195-0005-000-100K,195-0005-000; CDS_SEC: 1; CHIPS_PART_NAME: R; DEVICE_TYPENAME: R_0402-100K1625MW195-0005-000-100K195-0005-000; DRAWING: @P2597_C02_LIB.P2597_C02(SCH_1):PAGE30; MAX_WATTAGE: 62.5mW; NV_PN: 195-0005-000; PATH: I10; PHYS_PAGE: 30; ROT: 0; SEC: 1; SIGNAL_MODEL: nv_res; TOL: 1%; VER: 2; XY: (-9750,4500)
R95 = R#1: ASSEMBLY: PWR_DIS; CDS_LIB: discrete; CDS_PART_NAME: R_0402-0OHM,0.05 OHM,62.5MW,195-2655-000; CDS_PHYS_PART_NAME: R_0402-0OHM,0.05 OHM,62.5MW,195-2655-000-0OHM,195-2655-000; CDS_SEC: 1; CHIPS_PART_NAME: R; DEVICE_TYPENAME: R_0402-0OHM005OHM625MW195-2655-000-0OHM195-2655-000; DRAWING: @P2597_C02_LIB.P2597_C02(SCH_1):PAGE30; MAX_WATTAGE: 62.5mW; NV_PN: 195-2655-000; PATH: I40; PHYS_PAGE: 30; ROT: 0; SEC: 1; SIGNAL_MODEL: nv_res; TOL: 0.05 ohm; VER: 2; XY: (-7100,5650)
R98 = R#1: ASSEMBLY: PWR_DIS; CDS_LIB: discrete; CDS_PART_NAME: R_0402-10K,5 %,62.5MW,195-0486-000; CDS_PHYS_PART_NAME: R_0402-10K,5 %,62.5MW,195-0486-000-10K,195-0486-000; CDS_SEC: 1; CHIPS_PART_NAME: R; DEVICE_TYPENAME: R_0402-10K5625MW195-0486-000-10K195-0486-000; DRAWING: @P2597_C02_LIB.P2597_C02(SCH_1):PAGE30; MAX_WATTAGE: 62.5mW; NV_PN: 195-0486-000; PATH: I55; PHYS_PAGE: 30; ROT: 0; SEC: 1; SIGNAL_MODEL: nv_res; TOL: 5%; VER: 2; XY: (-10900,5800)
R105 = R#1: ASSEMBLY: PWR_DIS; CDS_LIB: discrete; CDS_PART_NAME: R_0402-20K,1 %,62.5MW,195-0150-000; CDS_PHYS_PART_NAME: R_0402-20K,1 %,62.5MW,195-0150-000-195-0150-000,20K; CDS_SEC: 1; CHIPS_PART_NAME: R; DEVICE_TYPENAME: R_0402-20K1625MW195-0150-000-195-0150-00020K; DRAWING: @P2597_C02_LIB.P2597_C02(SCH_1):PAGE30; MAX_WATTAGE: 62.5mW; NV_PN: 195-0150-000; PATH: I3; PHYS_PAGE: 30; ROT: 0; SEC: 1; SIGNAL_MODEL: nv_res; TOL: 1%; VER: 2; XY: (-10250,4500)
C110 = C: ASSEMBLY: PWR_MON; CDS_LIB: discrete; CDS_PART_NAME: C_0402W-4.7UF,X5R,20%,4V,039-0145-000; CDS_PHYS_PART_NAME: C_0402W-4.7UF,X5R,20%,4V,039-0145-000-039-0145-000,4.7UF; CDS_SEC: 1; DEVICE_TYPENAME: C_0402W-47UFX5R204V039-0145-000-039-0145-00047UF; DRAWING: @P2597_C02_LIB.P2597_C02(SCH_1):PAGE31; MAT: X5R; MAX_VOLTAGE: 4V; NO_XNET_CONNECTION: 1; NV_PN: 039-0145-000; PACK_TYPE: 0402W; PATH: I37; PHYS_PAGE: 31; ROT: 0; SEC: 1; SIGNAL_MODEL: DEFAULT_CAPACITOR_1e+06pF_2_1; TOL: 20%; VER: 1; XY: (-5450,3100)
C111 = C: ASSEMBLY: PWR_MON; CDS_LIB: discrete; CDS_PART_NAME: C_0402W-4.7UF,X5R,20%,6.3V,039-0188-000; CDS_PHYS_PART_NAME: C_0402W-4.7UF,X5R,20%,6.3V,039-0188-000-039-0188-000,4.7UF; CDS_SEC: 1; DEVICE_TYPENAME: C_0402W-47UFX5R2063V039-0188-000-039-0188-00047UF; DRAWING: @P2597_C02_LIB.P2597_C02(SCH_1):PAGE31; MAT: X5R; MAX_VOLTAGE: 6.3V; NV_PN: 039-0188-000; PACK_TYPE: 0402W; PATH: I36; PHYS_PAGE: 31; ROT: 2; SEC: 1; SIGNAL_MODEL: DEFAULT_CAPACITOR_100000pF_2_1; TOL: 20%; VER: 1; XY: (-5450,2550)
C112 = C: ASSEMBLY: PWR_MON; CDS_LIB: discrete; CDS_PART_NAME: C_0402W-4.7UF,X5R,20%,6.3V,039-0188-000; CDS_PHYS_PART_NAME: C_0402W-4.7UF,X5R,20%,6.3V,039-0188-000-039-0188-000,4.7UF; CDS_SEC: 1; DEVICE_TYPENAME: C_0402W-47UFX5R2063V039-0188-000-039-0188-00047UF; DRAWING: @P2597_C02_LIB.P2597_C02(SCH_1):PAGE31; MAT: X5R; MAX_VOLTAGE: 6.3V; NV_PN: 039-0188-000; PACK_TYPE: 0402W; PATH: I41; PHYS_PAGE: 31; ROT: 2; SEC: 1; SIGNAL_MODEL: DEFAULT_CAPACITOR_100000pF_2_1; SKU: NO STUFF; TOL: 20%; VER: 1; XY: (-5450,3600)
C116 = C: ASSEMBLY: PWR_MON; CDS_LIB: discrete; CDS_PART_NAME: C_0402W-4.7UF,X5R,20%,6.3V,039-0188-000; CDS_PHYS_PART_NAME: C_0402W-4.7UF,X5R,20%,6.3V,039-0188-000-039-0188-000,4.7UF; CDS_SEC: 1; DEVICE_TYPENAME: C_0402W-47UFX5R2063V039-0188-000-039-0188-00047UF; DRAWING: @P2597_C02_LIB.P2597_C02(SCH_1):PAGE31; MAT: X5R; MAX_VOLTAGE: 6.3V; NV_PN: 039-0188-000; PACK_TYPE: 0402W; PATH: I82; PHYS_PAGE: 31; ROT: 0; SEC: 1; SEC_TYPE: 0402W; SIGNAL_MODEL: DEFAULT_CAPACITOR_100000pF_2_1; SKU: NO STUFF; TOL: 20%; VER: 1; XY: (-6050,4800)
C118 = C: ASSEMBLY: PWR_MON; CDS_LIB: discrete; CDS_PART_NAME: C_0402W-4.7UF,X5R,20%,4V,039-0145-000; CDS_PHYS_PART_NAME: C_0402W-4.7UF,X5R,20%,4V,039-0145-000-039-0145-000,4.7UF; CDS_SEC: 1; DEVICE_TYPENAME: C_0402W-47UFX5R204V039-0145-000-039-0145-00047UF; DRAWING: @P2597_C02_LIB.P2597_C02(SCH_1):PAGE31; MAT: X5R; MAX_VOLTAGE: 4V; NO_XNET_CONNECTION: 1; NV_PN: 039-0145-000; PACK_TYPE: 0402W; PATH: I48; PHYS_PAGE: 31; ROT: 0; SEC: 1; SEC_TYPE: 0402W; SIGNAL_MODEL: DEFAULT_CAPACITOR_1e+06pF_2_1; TOL: 20%; VER: 1; XY: (-5450,4350)
C123 = C: ASSEMBLY: PWR_MON; CDS_LIB: discrete; CDS_PART_NAME: C_0402W-4.7UF,X5R,20%,6.3V,039-0188-000; CDS_PHYS_PART_NAME: C_0402W-4.7UF,X5R,20%,6.3V,039-0188-000-039-0188-000,4.7UF; CDS_SEC: 1; DEVICE_TYPENAME: C_0402W-47UFX5R2063V039-0188-000-039-0188-00047UF; DRAWING: @P2597_C02_LIB.P2597_C02(SCH_1):PAGE31; MAT: X5R; MAX_VOLTAGE: 6.3V; NV_PN: 039-0188-000; PACK_TYPE: 0402W; PATH: I83; PHYS_PAGE: 31; ROT: 0; SEC: 1; SEC_TYPE: 0402W; SIGNAL_MODEL: DEFAULT_CAPACITOR_100000pF_2_1; SKU: NO STUFF; TOL: 20%; VER: 1; XY: (-6050,4000)
C129 = C: ASSEMBLY: PWR_MON; CDS_LIB: discrete; CDS_PART_NAME: C_1206-4.7UF,X5R,10%,25V,039-0093-000; CDS_PHYS_PART_NAME: C_1206-4.7UF,X5R,10%,25V,039-0093-000-039-0093-000,4.7UF; CDS_SEC: 1; DEVICE_TYPENAME: C_1206-47UFX5R1025V039-0093-000-039-0093-00047UF; DRAWING: @P2597_C02_LIB.P2597_C02(SCH_1):PAGE31; MAT: X5R; MAX_VOLTAGE: 25V; NV_PN: 039-0093-000; PATH: I55; PHYS_PAGE: 31; ROT: 0; SEC: 1; SIGNAL_MODEL: nv_cap; SKU: NO STUFF; TOL: 10%; VER: 1; XY: (-5450,5700)
C130 = C: ASSEMBLY: PWR_MON; CDS_LIB: discrete; CDS_PART_NAME: C_1206-4.7UF,X5R,10%,25V,039-0093-000; CDS_PHYS_PART_NAME: C_1206-4.7UF,X5R,10%,25V,039-0093-000-039-0093-000,4.7UF; CDS_SEC: 1; DEVICE_TYPENAME: C_1206-47UFX5R1025V039-0093-000-039-0093-00047UF; DRAWING: @P2597_C02_LIB.P2597_C02(SCH_1):PAGE31; MAT: X5R; MAX_VOLTAGE: 25V; NV_PN: 039-0093-000; PATH: I50; PHYS_PAGE: 31; ROT: 0; SEC: 1; SIGNAL_MODEL: nv_cap; SKU: NO STUFF; TOL: 10%; VER: 1; XY: (-5450,5050)
C132 = C: ASSEMBLY: PWR_MON; CDS_LIB: discrete; CDS_PART_NAME: C_0402W-4.7UF,X5R,20%,4V,039-0145-000; CDS_PHYS_PART_NAME: C_0402W-4.7UF,X5R,20%,4V,039-0145-000-039-0145-000,4.7UF; CDS_SEC: 1; DEVICE_TYPENAME: C_0402W-47UFX5R204V039-0145-000-039-0145-00047UF; DRAWING: @P2597_C02_LIB.P2597_C02(SCH_1):PAGE31; MAT: X5R; MAX_VOLTAGE: 4V; NO_XNET_CONNECTION: 1; NV_PN: 039-0145-000; PACK_TYPE: 0402W; PATH: I54; PHYS_PAGE: 31; ROT: 0; SEC: 1; SEC_TYPE: 0402W; SIGNAL_MODEL: DEFAULT_CAPACITOR_1e+06pF_2_1; TOL: 20%; VER: 1; XY: (-5450,5400)
C505 = C: ASSEMBLY: PWR_MON; CDS_LIB: discrete; CDS_PART_NAME: C_0402-0.1UF,X5R,10%,6.3V,039-0007-000; CDS_PHYS_PART_NAME: C_0402-0.1UF,X5R,10%,6.3V,039-0007-000-0.1UF,039-0007-000; CDS_SEC: 1; DEVICE_TYPENAME: C_0402-01UFX5R1063V039-0007-000-01UF039-0007-000; DRAWING: @P2597_C02_LIB.P2597_C02(SCH_1):PAGE31; MAT: X5R; MAX_VOLTAGE: 6.3V; NV_PN: 039-0007-000; PATH: I17; PHYS_PAGE: 31; ROT: 0; SEC: 1; SIGNAL_MODEL: DEFAULT_CAPACITOR_100000pF_2_1; TOL: 10%; VER: 1; XY: (-8350,4800)
R179 = R: ASSEMBLY: PWR_MON; CDS_LIB: discrete; CDS_PART_NAME: R_0402-10OHM,1 %,62.5MW,195-0001-000; CDS_PHYS_PART_NAME: R_0402-10OHM,1 %,62.5MW,195-0001-000-10OHM,195-0001-000; CDS_SEC: 1; DEVICE_TYPENAME: R_0402-10OHM1625MW195-0001-000-10OHM195-0001-000; DRAWING: @P2597_C02_LIB.P2597_C02(SCH_1):PAGE31; MAX_WATTAGE: 62.5mW; NV_PN: 195-0001-000; PATH: I40; PHYS_PAGE: 31; ROT: 0; SEC: 1; SIGNAL_MODEL: nv_res; TOL: 1%; VER: 1; XY: (-4750,2900)
R180 = R: ASSEMBLY: PWR_MON; CDS_LIB: discrete; CDS_PART_NAME: R_0402-10OHM,1 %,62.5MW,195-0001-000; CDS_PHYS_PART_NAME: R_0402-10OHM,1 %,62.5MW,195-0001-000-10OHM,195-0001-000; CDS_SEC: 1; DEVICE_TYPENAME: R_0402-10OHM1625MW195-0001-000-10OHM195-0001-000; DRAWING: @P2597_C02_LIB.P2597_C02(SCH_1):PAGE31; MAX_WATTAGE: 62.5mW; NV_PN: 195-0001-000; PATH: I43; PHYS_PAGE: 31; ROT: 0; SEC: 1; SIGNAL_MODEL: nv_res; TOL: 1%; VER: 1; XY: (-4750,3250)
R185 = R: ASSEMBLY: PWR_MON; CDS_LIB: discrete; CDS_PART_NAME: R_0402-680K,5 %,62.5MW,195-0628-000; CDS_PHYS_PART_NAME: R_0402-680K,5 %,62.5MW,195-0628-000-195-0628-000,680K; CDS_SEC: 1; DEVICE_TYPENAME: R_0402-680K5625MW195-0628-000-195-0628-000680K; DRAWING: @P2597_C02_LIB.P2597_C02(SCH_1):PAGE31; MAX_WATTAGE: 62.5mW; NV_PN: 195-0628-000; PATH: I105; PHYS_PAGE: 31; ROT: 0; SEC: 1; SIGNAL_MODEL: nv_res; TOL: 5%; VER: 1; XY: (-6500,3650)
R191 = R: ASSEMBLY: PWR_MON; CDS_LIB: discrete; CDS_PART_NAME: R_0402-0OHM,0.05 OHM,62.5MW,195-2655-000; CDS_PHYS_PART_NAME: R_0402-0OHM,0.05 OHM,62.5MW,195-2655-000-0OHM,195-2655-000; CDS_SEC: 1; DEVICE_TYPENAME: R_0402-0OHM005OHM625MW195-2655-000-0OHM195-2655-000; DRAWING: @P2597_C02_LIB.P2597_C02(SCH_1):PAGE31; MAX_WATTAGE: 62.5mW; NV_PN: 195-2655-000; PATH: I80; PHYS_PAGE: 31; ROT: 0; SEC: 1; SIGNAL_MODEL: nv_res; TOL: 0.05 ohm; VER: 1; XY: (-7900,2650)
R195 = R: ASSEMBLY: PWR_MON; CDS_LIB: discrete; CDS_PART_NAME: R_0402-680K,5 %,62.5MW,195-0628-000; CDS_PHYS_PART_NAME: R_0402-680K,5 %,62.5MW,195-0628-000-195-0628-000,680K; CDS_SEC: 1; DEVICE_TYPENAME: R_0402-680K5625MW195-0628-000-195-0628-000680K; DRAWING: @P2597_C02_LIB.P2597_C02(SCH_1):PAGE31; MAX_WATTAGE: 62.5mW; NV_PN: 195-0628-000; PATH: I104; PHYS_PAGE: 31; ROT: 0; SEC: 1; SIGNAL_MODEL: nv_res; TOL: 5%; VER: 1; XY: (-6200,4400)
R197 = R: ASSEMBLY: PWR_MON; CDS_LIB: discrete; CDS_PART_NAME: R_0402-0OHM,0.05 OHM,62.5MW,195-2655-000; CDS_PHYS_PART_NAME: R_0402-0OHM,0.05 OHM,62.5MW,195-2655-000-0OHM,195-2655-000; CDS_SEC: 1; DEVICE_TYPENAME: R_0402-0OHM005OHM625MW195-2655-000-0OHM195-2655-000; DRAWING: @P2597_C02_LIB.P2597_C02(SCH_1):PAGE31; MAX_WATTAGE: 62.5mW; NV_PN: 195-2655-000; PATH: I99; PHYS_PAGE: 31; ROT: 0; SEC: 1; SIGNAL_MODEL: nv_res; TOL: 0.05 ohm; VER: 1; XY: (-8050,4250)
R199 = R: ASSEMBLY: PWR_MON; CDS_LIB: discrete; CDS_PART_NAME: R_0402-10OHM,1 %,62.5MW,195-0001-000; CDS_PHYS_PART_NAME: R_0402-10OHM,1 %,62.5MW,195-0001-000-10OHM,195-0001-000; CDS_SEC: 1; DEVICE_TYPENAME: R_0402-10OHM1625MW195-0001-000-10OHM195-0001-000; DRAWING: @P2597_C02_LIB.P2597_C02(SCH_1):PAGE31; MAX_WATTAGE: 62.5mW; NV_PN: 195-0001-000; PATH: I51; PHYS_PAGE: 31; ROT: 0; SEC: 1; SIGNAL_MODEL: nv_res; TOL: 1%; VER: 1; XY: (-4750,4500)
R201 = R: ASSEMBLY: PWR_MON; CDS_LIB: discrete; CDS_PART_NAME: R_0402-10OHM,1 %,62.5MW,195-0001-000; CDS_PHYS_PART_NAME: R_0402-10OHM,1 %,62.5MW,195-0001-000-10OHM,195-0001-000; CDS_SEC: 1; DEVICE_TYPENAME: R_0402-10OHM1625MW195-0001-000-10OHM195-0001-000; DRAWING: @P2597_C02_LIB.P2597_C02(SCH_1):PAGE31; MAX_WATTAGE: 62.5mW; NV_PN: 195-0001-000; PATH: I47; PHYS_PAGE: 31; ROT: 0; SEC: 1; SIGNAL_MODEL: nv_res; TOL: 1%; VER: 1; XY: (-4750,4150)
R211 = R: ASSEMBLY: PWR_MON; CDS_LIB: discrete; CDS_PART_NAME: R_0402-680K,5 %,62.5MW,195-0628-000; CDS_PHYS_PART_NAME: R_0402-680K,5 %,62.5MW,195-0628-000-195-0628-000,680K; CDS_SEC: 1; DEVICE_TYPENAME: R_0402-680K5625MW195-0628-000-195-0628-000680K; DRAWING: @P2597_C02_LIB.P2597_C02(SCH_1):PAGE31; MAX_WATTAGE: 62.5mW; NV_PN: 195-0628-000; PATH: I101; PHYS_PAGE: 31; ROT: 0; SEC: 1; SIGNAL_MODEL: nv_res; TOL: 5%; VER: 1; XY: (-6650,5850)
R213 = R: ASSEMBLY: PWR_MON; CDS_LIB: discrete; CDS_PART_NAME: R_0402-10OHM,1 %,62.5MW,195-0001-000; CDS_PHYS_PART_NAME: R_0402-10OHM,1 %,62.5MW,195-0001-000-10OHM,195-0001-000; CDS_SEC: 1; DEVICE_TYPENAME: R_0402-10OHM1625MW195-0001-000-10OHM195-0001-000; DRAWING: @P2597_C02_LIB.P2597_C02(SCH_1):PAGE31; MAX_WATTAGE: 62.5mW; NV_PN: 195-0001-000; PATH: I57; PHYS_PAGE: 31; ROT: 0; SEC: 1; SIGNAL_MODEL: nv_res; TOL: 1%; VER: 1; XY: (-4750,5550)
R214 = R: ASSEMBLY: PWR_MON; CDS_LIB: discrete; CDS_PART_NAME: R_0402-10OHM,1 %,62.5MW,195-0001-000; CDS_PHYS_PART_NAME: R_0402-10OHM,1 %,62.5MW,195-0001-000-10OHM,195-0001-000; CDS_SEC: 1; DEVICE_TYPENAME: R_0402-10OHM1625MW195-0001-000-10OHM195-0001-000; DRAWING: @P2597_C02_LIB.P2597_C02(SCH_1):PAGE31; MAX_WATTAGE: 62.5mW; NV_PN: 195-0001-000; PATH: I53; PHYS_PAGE: 31; ROT: 0; SEC: 1; SIGNAL_MODEL: nv_res; TOL: 1%; VER: 1; XY: (-4750,5200)
U18 = U_PWRMTR_INA3221: ASSEMBLY: PWR_MON; CDS_LIB: digital; CDS_PART_NAME: U_PWRMTR_INA3221_QFN16-INA3221AIRGVR,-9999V..9999V,-9999V..9999V,9999A,MONITOR,115-1066-000; CDS_PHYS_PART_NAME: U_PWRMTR_INA3221_QFN16-INA3221AIRGVR,-9999V..9999V,-9999V..9999V,9999A,MONITOR,115-1066-000-115-1066-000; CDS_SEC: 1; DEVICE_TYPENAME: U_PWRMTR_INA3221_QFN16-INA3221AIRGVR-9999V9999V-9999V9999V9999AMONITOR115-1066-000-115-1066-000; DRAWING: @P2597_C02_LIB.P2597_C02(SCH_1):PAGE31; MAX_CURRENT: 9999A; MAX_VOLTAGE: -9999V..9999V; NV_NAME: INA3221AIRGVR; NV_PN: 115-1066-000; OUTPUT_VOLTAGE: -9999V..9999V; PACK_TYPE: QFN16; PATH: I13; PHYS_PAGE: 31; ROT: 0; SEC: 1; SEC_TYPE: QFN16; TYPE: Monitor; VER: 1; XY: (-7450,3850)

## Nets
GND: C49.2 C52.2 C53.2 C201.2 C505.2 Q6.2(S) Q8.2(S) Q9.2(S) Q11.2(S) Q12.2(S) Q13.2(S) R63.2 R78.2 R88.2 R94.2 R98.2 R105.2 R191.2 U18.TP(PAD) ; also on sheet 1 2 5 6 7 9 10 11 12 13 14 15 16 17 18 19 20 21 22 23 24 25 26 30
VDD_1V8: R75.1 ; also on sheet 5 9 10 12 13 16 17 18 19 20 22 24 30
VDD_1V8_DISCHARGE: Q12.3(D) R75.2
VDD_3V3_DISCHARGE: Q9.3(D) R65.2
VDD_3V3_SLP: R57.1 ; also on sheet 5 11 16 17 20 21 22 25
VDD_3V3_SLP_DISCHARGE: Q6.3(D) R57.2
VDD_3V3_SYS: C505.1 R65.1 U18.4(VS) ; also on sheet 1 2 5 6 12 13 17 18 19 23 24 25
VDD_3V3_SYS_FILTER_N: C110.2 C111.1 R179.1 U18.1(VIN3N)
VDD_3V3_SYS_FILTER_P: C110.1 C112.2 R180.1 R185.1 U18.2(VIN3P)
VDD_3V3_SYS_N: R179.2 ; also on sheet 6
VDD_3V3_SYS_P: R180.2 ; also on sheet 6
VDD_5V0_DISCHARGE: Q8.3(D) R64.2
VDD_5V0_IO_SYS: R64.1 ; also on sheet 5 6 9 11 12 16 17 18 20 22 26 30
VDD_5V_IO_SYS_F_N: C118.2 C123.1 R201.1 U18.14(VIN2N)
VDD_5V_IO_SYS_F_P: C116.2 C118.1 R195.1 R199.1 U18.15(VIN2P)
VDD_5V_IO_SYS_N: R201.2 ; also on sheet 6
VDD_5V_IO_SYS_P: R199.2 ; also on sheet 6
VDD_MUX: D7.3(AA) R77.1 R98.1 ; also on sheet 6 7 17
VDD_MUX_CAP: D7.1(C1) Q14.2(E) R90.1
VDD_MUX_CAP_R: C52.1 C53.1 R88.1 R90.2
VDD_MUX_FILTER_M: C130.1 C132.2 R214.1 U18.11(VIN1N)
VDD_MUX_FILTER_P: C129.2 C132.1 R211.1 R213.1 U18.12(VIN1P)
VDD_MUX_N: R214.2 ; also on sheet 7
VDD_MUX_P: R213.2 ; also on sheet 7
VIN_PWR_BAD_L: R95.1 ; also on sheet 6 7 30
VIN_PWR_BAD_R_L: Q13.3(D) R95.2
CARRIER_PWR_ON: Q11.1(G) ; also on sheet 6 14 15 30
DIS_PNP_B: C201.1 D7.2(C2) Q14.1(B) R105.1
DIS_PNP_C: Q14.3(C) R93.1
DISCHARGE: D5.3(CC) Q6.1(G) Q8.1(G) Q9.1(G) Q12.1(G) R63.1 ; also on sheet 22
DISCHARGE_CAR: D5.1(A1) Q11.3(D) R77.2 R78.1
DISCHARGE_CAT: C49.1 D5.2(A2) Q13.1(G) R93.2 R94.1
I2C_GP1_CLK_3V3: U18.6(SCL) ; also on sheet 2 12 13 17 18 19 30
I2C_GP1_DAT_3V3: R197.1 U18.7(SDA) ; also on sheet 2 12 13 17 18 19 30
INA_1_A0: R197.2 U18.5(A0)
PMGND: C111.2 C112.1 C116.1 C123.2 C129.1 C130.2 R185.2 R191.1 R195.2 R211.2 U18.3(GND)
SNN_CRIT_1: U18.9(CRITICAL*)
SNN_PM_PV_2: U18.10(PV)
SNN_PM_TC_2: U18.13(TC)
SNN_PM_VPU_2: U18.16(VPU)
SNN_WARN_1: U18.8(WARNING*)

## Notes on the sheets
sheet 3
- A
- B
- C
- D
- E
- F
- G
- H
- POWER MONITORS I
- 1
- 1
- DC JACK to IO board
- 2
- 2
- 5V SYSTEM
- I2C Gen 2 : 7'h42
- 3
- 3
- 3V3 SYSTEM
- 4
- 4
- 5
- 5
- NVIDIA CORPORATION
- 2701 SAN TOMAS EXPRESSWAY
- ASSEMBLY
- <ASSEMBLY_DESCRIPTION>
- SANTA CLARA, CA 95050, USA
- PAGE DETAIL
- Power Monitor I
- NV_PN
- 600-82597-BASE-900
- ALL NVIDIA DESIGN SPECIFICATIONS, REFERENCE SPECIFICATIONS, REFERENCE BOARDS, FILES, DRAWINGS, DIAGNOSTICS, LISTS AND OTHER DOCUMENTS OR INFORMATION (TOGETHER AND SEPARATELY, 'MATERIALS') ARE BEING PROVIDED 'AS IS'. THE MATERIALS MAY
- CONTAIN KNOWN AND UNKNOWN VIOLATIONS OR DEVIATIONS OF INDUSTRY STANDARDS AND SPECIFICATIONS. NVIDIA MAKES NO WARRANTIES, EXPRESSED, IMPLIED, STATUTORY OR OTHERWISE WITH RESPECT TO THE MATERIALS OR OTHERWISE, AND EXPRESSLY DISCLAIMS ALL
- PCB REV
- P2597-C02
- PAGE
- 31 OF 34
- IMPLIED WARRANTIES INCLUDING, WITHOUT LIMITATION, THE WARRANTIES OF DESIGN, OF NONINFRINGEMENT, MERCHANTABILITY OR FITNESS FOR A PARTICULAR PURPOSE, OR ARISING FROM A COURSE OF DEALING, TRADE USAGE, TRADE PRACTICE, OR INDUSTRY STANDARDS.
- BOM REV
- A
- DATE
- 23-OCT-2017
- A
- B
- C
- D
- E
- F
- G
- H
sheet 4
- A
- B
- C
- D
- E
- F
- G
- H
- RAIL DISCHARGE
- 1
- 1
- 2
- 2
- 3
- 3
- NS
- 4
- 4
- 5
- 5
- NVIDIA CORPORATION
- 2701 SAN TOMAS EXPRESSWAY
- ASSEMBLY
- <ASSEMBLY_DESCRIPTION>
- SANTA CLARA, CA 95050, USA
- PAGE DETAIL
- Rail Discharge
- NV_PN
- 600-82597-BASE-900
- ALL NVIDIA DESIGN SPECIFICATIONS, REFERENCE SPECIFICATIONS, REFERENCE BOARDS, FILES, DRAWINGS, DIAGNOSTICS, LISTS AND OTHER DOCUMENTS OR INFORMATION (TOGETHER AND SEPARATELY, 'MATERIALS') ARE BEING PROVIDED 'AS IS'. THE MATERIALS MAY
- CONTAIN KNOWN AND UNKNOWN VIOLATIONS OR DEVIATIONS OF INDUSTRY STANDARDS AND SPECIFICATIONS. NVIDIA MAKES NO WARRANTIES, EXPRESSED, IMPLIED, STATUTORY OR OTHERWISE WITH RESPECT TO THE MATERIALS OR OTHERWISE, AND EXPRESSLY DISCLAIMS ALL
- PCB REV
- P2597-C02
- PAGE
- 30 OF 34
- IMPLIED WARRANTIES INCLUDING, WITHOUT LIMITATION, THE WARRANTIES OF DESIGN, OF NONINFRINGEMENT, MERCHANTABILITY OR FITNESS FOR A PARTICULAR PURPOSE, OR ARISING FROM A COURSE OF DEALING, TRADE USAGE, TRADE PRACTICE, OR INDUSTRY STANDARDS.
- BOM REV
- A
- DATE
- 23-OCT-2017
- A
- B
- C
- D
- E
- F
- G
- H
